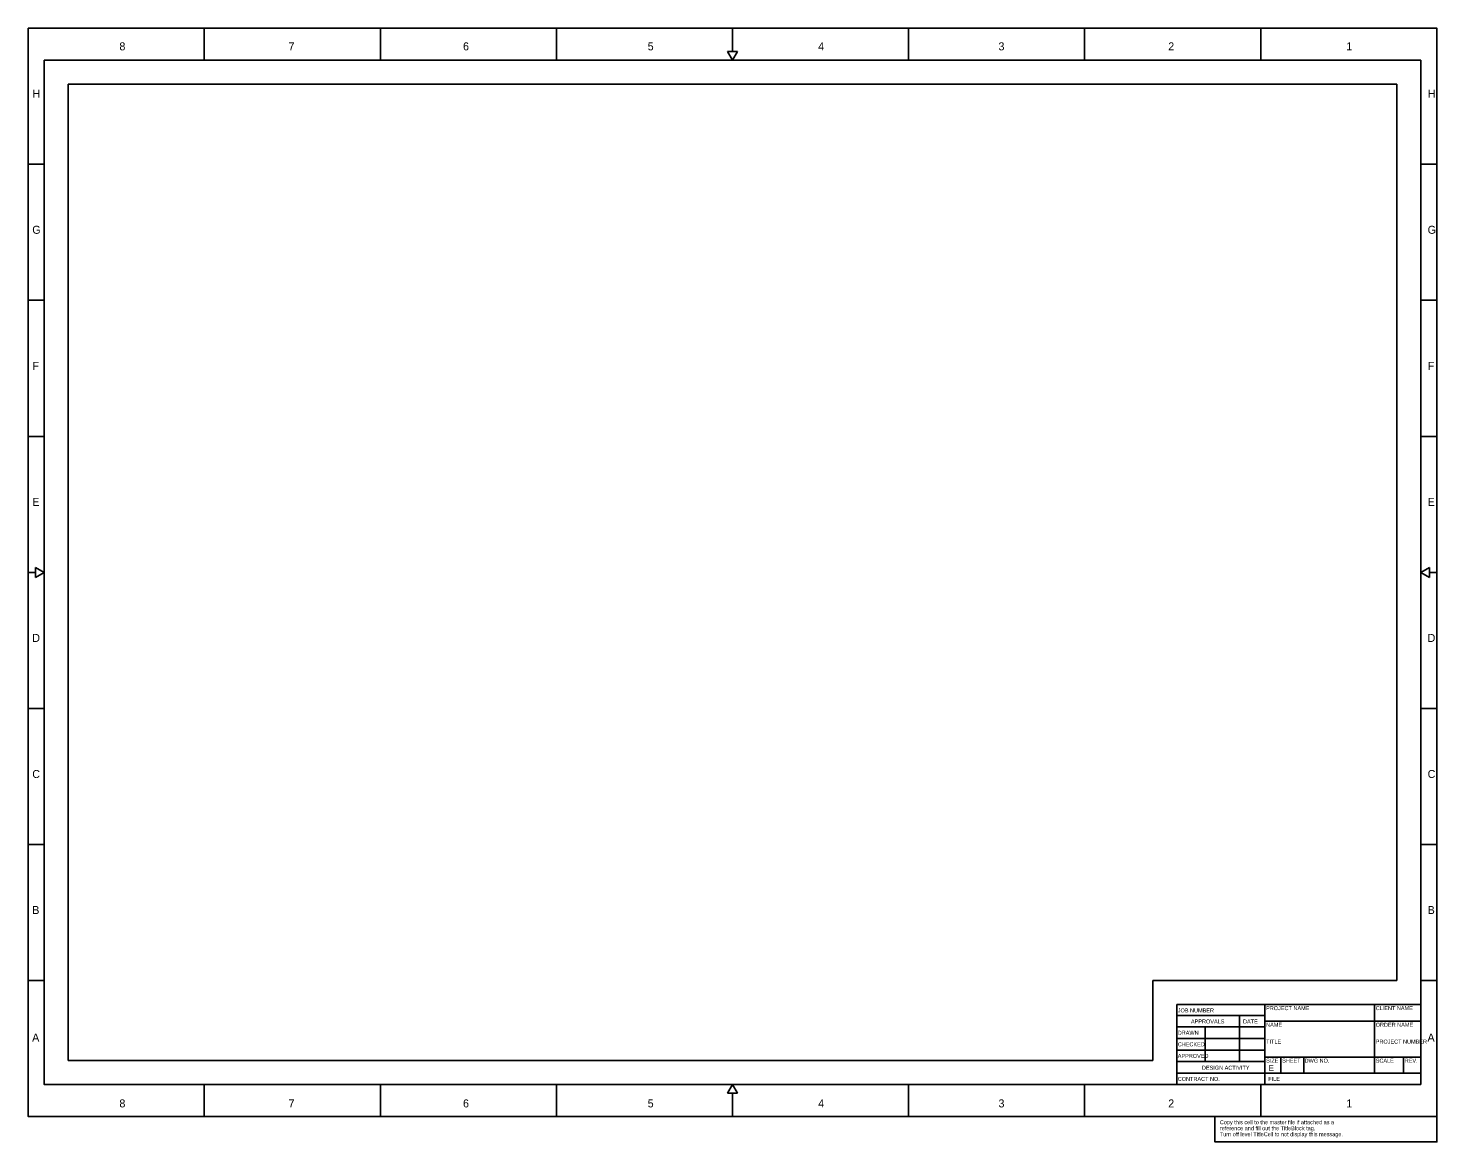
# Model space of a CAD drawing. Extents: x 0 to 3.67, y -0.07 to 2.83.
import ezdxf

# ---------------------------------------------------------------- set-up
doc = ezdxf.new("R2010")
doc.units = 0
for name, color, linetype in [('Border', 7, 'Continuous'), ('BorderPlot', 7, 'Continuous'), ('ClipShape', 7, 'Continuous'), ('TitleBlock', 7, 'Continuous'), ('TitleBlockText', 7, 'Continuous'), ('TitleCell', 7, 'Continuous')]:
    doc.layers.add(name, color=color, linetype=linetype)

msp = doc.modelspace()

# ---------------------------------------------------------------- linework, layer by layer
at = {"layer": 'Border'}
for p, q in [((0.4583, 2.8333), (0.4583, 2.75)), ((0.9167, 2.8333), (0.9167, 2.75)), ((1.375, 2.8333), (1.375, 2.75)), ((1.8333, 2.7726), (1.8333, 2.8333)), ((2.2917, 2.8333), (2.2917, 2.75)), ((2.75, 2.8333), (2.75, 2.75)), ((3.2083, 2.8333), (3.2083, 2.75)), ((1.8333, 2.75), (1.8203, 2.7726)), ((1.8203, 2.7726), (1.8464, 2.7726)), ((1.8333, 2.75), (1.8464, 2.7726)), ((0.0417, 2.4792), (0, 2.4792)), ((3.625, 2.4792), (3.6667, 2.4792)), ((0.0417, 2.125), (0, 2.125)), ((3.625, 2.125), (3.6667, 2.125)), ((0.0417, 1.7708), (0, 1.7708)), ((3.625, 1.7708), (3.6667, 1.7708)), ((0.0191, 1.4167), (0, 1.4167)), ((0.0417, 1.4167), (0.0191, 1.4297)), ((0.0191, 1.4297), (0.0191, 1.4036)), ((0.0191, 1.4036), (0.0417, 1.4167)), ((3.625, 1.4167), (3.6476, 1.4297)), ((3.6476, 1.4036), (3.625, 1.4167)), ((3.6476, 1.4297), (3.6476, 1.4036)), ((3.6476, 1.4167), (3.6667, 1.4167)), ((0.0417, 1.0625), (0, 1.0625)), ((3.625, 1.0625), (3.6667, 1.0625)), ((0.0417, 0.7083), (0, 0.7083)), ((3.625, 0.7083), (3.6667, 0.7083)), ((0.0417, 0.3542), (0, 0.3542)), ((3.625, 0.3542), (3.6667, 0.3542)), ((0.4583, 0), (0.4583, 0.0833)), ((0.9167, 0), (0.9167, 0.0833)), ((1.375, 0), (1.375, 0.0833)), ((1.8333, 0.0833), (1.8203, 0.0607)), ((1.8333, 0.0833), (1.8464, 0.0607)), ((2.2917, 0), (2.2917, 0.0833)), ((2.75, 0), (2.75, 0.0833)), ((3.2083, 0), (3.2083, 0.0833)), ((1.8203, 0.0607), (1.8464, 0.0607)), ((1.8333, 0.0607), (1.8333, 0))]:
    msp.add_line(p, q, dxfattribs=at)
msp.add_lwpolyline([(3.625, 0.0833), (0.0417, 0.0833), (0.0417, 2.75), (3.625, 2.75)], close=True, dxfattribs=at)
at = {"layer": 'BorderPlot'}
msp.add_lwpolyline([(0, 2.8333), (3.6667, 2.8333), (3.6667, 0), (0, 0)], close=True, dxfattribs=at)
at = {"layer": 'ClipShape'}
for p, q in [((0.1042, 0.1458), (0.1042, 2.6875)), ((0.1042, 2.6875), (3.5625, 2.6875)), ((3.5625, 2.6875), (3.5625, 0.3542)), ((3.5625, 0.3542), (2.9275, 0.3542)), ((2.9275, 0.3542), (2.9275, 0.1458)), ((2.9275, 0.1458), (0.1042, 0.1458))]:
    msp.add_line(p, q, dxfattribs=at)
at = {"layer": 'TitleBlock'}
for p, q in [((2.99, 0.0833), (2.99, 0.2917)), ((2.99, 0.2917), (3.625, 0.2917)), ((2.99, 0.2633), (3.2192, 0.2633)), ((3.1532, 0.1433), (3.1532, 0.2633)), ((3.2192, 0.0833), (3.2192, 0.2917)), ((3.5043, 0.1133), (3.5043, 0.2917)), ((2.99, 0.2333), (3.2192, 0.2333)), ((3.0633, 0.1433), (3.0633, 0.2333)), ((3.2192, 0.2483), (3.625, 0.2483)), ((2.99, 0.2033), (3.2192, 0.2033)), ((2.99, 0.1733), (3.2192, 0.1733)), ((3.2192, 0.155), (3.625, 0.155)), ((3.2608, 0.1133), (3.2608, 0.155)), ((3.3201, 0.1133), (3.3201, 0.155)), ((3.5799, 0.1133), (3.5799, 0.155)), ((2.99, 0.1433), (3.2192, 0.1433)), ((2.99, 0.1133), (3.625, 0.1133)), ((3.625, 0.0833), (3.625, 0.0833))]:
    msp.add_line(p, q, dxfattribs=at)
at = {"layer": 'TitleCell'}
msp.add_lwpolyline([(3.0889, 0), (3.6667, 0), (3.6667, -0.0657), (3.0889, -0.0657)], close=True, dxfattribs=at)

# ---------------------------------------------------------------- texts
at = {"layer": 'Border'}
for s, p in [('8', (0.2375, 2.7756)), ('7', (0.6777, 2.7756)), ('6', (1.1319, 2.7756)), ('5', (1.6126, 2.7756)), ('4', (2.0564, 2.7756)), ('3', (2.5257, 2.7756)), ('2', (2.9675, 2.7756)), ('1', (3.431, 2.7756)), ('H', (0.0112, 2.6523)), ('H', (3.6433, 2.6523)), ('G', (0.0107, 2.2981)), ('G', (3.6428, 2.2981)), ('F', (0.0112, 1.9439)), ('F', (3.6433, 1.9439)), ('E', (0.0108, 1.5898)), ('E', (3.6428, 1.5898)), ('D', (0.0107, 1.2356)), ('D', (3.6427, 1.2356)), ('C', (0.0107, 0.8814)), ('C', (3.6428, 0.8814)), ('B', (0.0107, 0.5273)), ('B', (3.6428, 0.5273)), ('A', (0.0104, 0.1954)), ('A', (3.6424, 0.1954)), ('8', (0.2375, 0.0239)), ('7', (0.6777, 0.0239)), ('6', (1.1319, 0.0239)), ('5', (1.6126, 0.0239)), ('4', (2.0564, 0.0239)), ('3', (2.5257, 0.0239)), ('2', (2.9675, 0.0239)), ('1', (3.431, 0.0239))]:
    msp.add_text(s, height=0.0208, dxfattribs=at).set_placement(p)
at = {"layer": 'TitleBlock'}
msp.add_text('E', height=0.0156, dxfattribs=at).set_placement((3.2287, 0.1183))
at = {"layer": 'TitleBlockText'}
for s, height, p in [('JOB NUMBER', 0.01042, (2.9923, 0.2712)), ('PROJECT NAME', 0.010417, (3.2223, 0.2771)), ('CLIENT NAME', 0.010417, (3.5076, 0.2771)), ('DRAWN', 0.01042, (2.9923, 0.2131)), ('APPROVALS', 0.01042, (3.0267, 0.2425)), ('DATE', 0.01042, (3.1622, 0.2425)), ('NAME', 0.01042, (3.2223, 0.2338)), ('ORDER NAME', 0.01042, (3.5076, 0.2338)), ('CHECKED', 0.01042, (2.9923, 0.1829)), ('TITLE', 0.01042, (3.2223, 0.19)), ('PROJECT NUMBER', 0.010417, (3.5076, 0.19)), ('APPROVED', 0.01042, (2.9923, 0.1528)), ('SIZE', 0.01042, (3.2223, 0.1404)), ('SHEET', 0.01042, (3.264, 0.1404)), ('DWG NO.', 0.01042, (3.3224, 0.1404)), ('SCALE', 0.01042, (3.5076, 0.1404)), ('REV.', 0.01042, (3.5832, 0.1404)), ('DESIGN ACTIVITY', 0.010417, (3.0552, 0.122)), ('CONTRACT NO.', 0.010417, (2.9923, 0.0928)), ('FILE', 0.01042, (3.2278, 0.093))]:
    msp.add_text(s, height=height, dxfattribs=at).set_placement(p)
at = {"layer": 'TitleCell'}
for s, p in [('Copy this cell to the master file if attached as a ', (3.1018, -0.0198)), ('reference and fill out the TitleBlock tag.', (3.1018, -0.0355)), ('Turn off level TitleCell to not display this message.', (3.1018, -0.0511))]:
    msp.add_text(s, height=0.010417, dxfattribs=at).set_placement(p)

doc.saveas('drawing.dxf')
